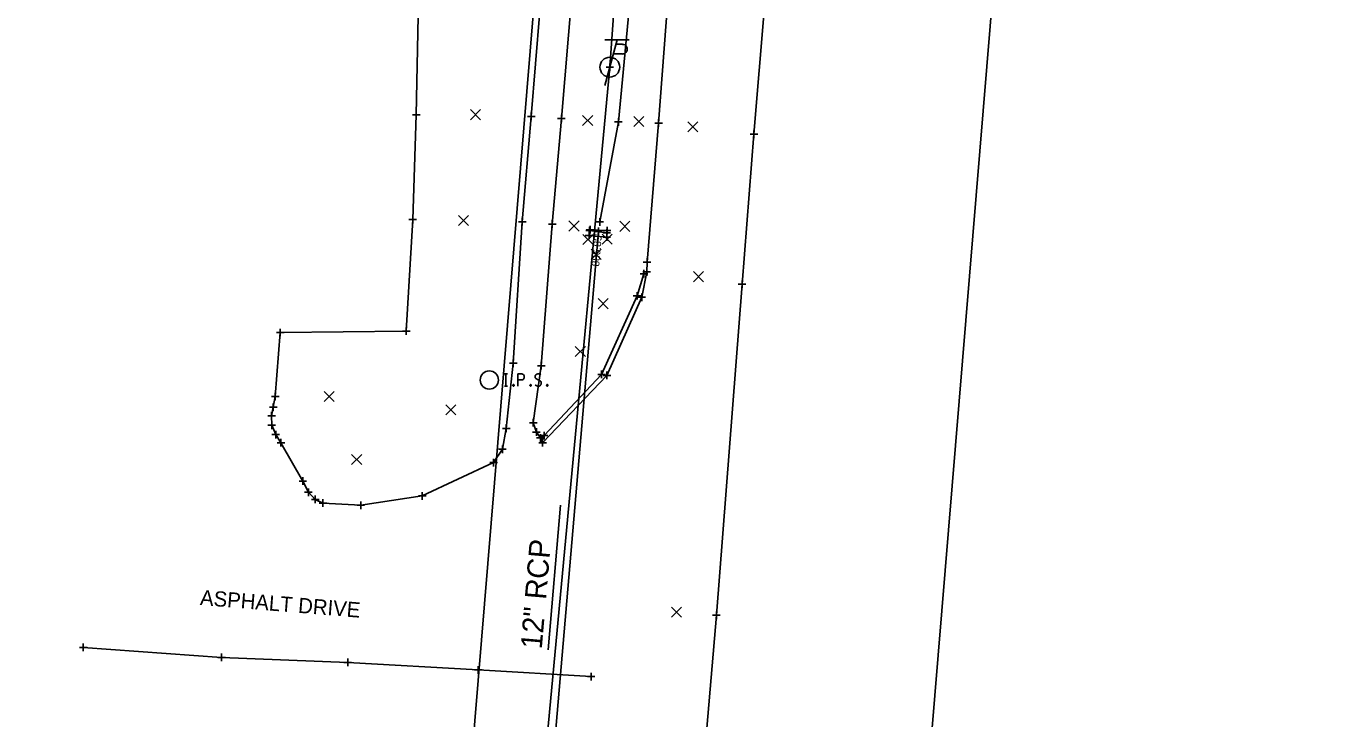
# Model space of a CAD drawing. Extents: x 1380550 to 1381945, y 468927 to 470496.
# Drawn here: x 1381495.3 to 1381668.4, y 469802 to 469893 of the extents above; entities that cross this region are included whole.
import ezdxf

# ---------------------------------------------------------------- set-up
doc = ezdxf.new("R2010")
doc.units = 0
for name, color, linetype in [('DR_X_Ditch', 7, 'Continuous'), ('DR_X_Elev_Flow', 7, 'Continuous'), ('DR_X_Storm_Sewer', 7, 'Continuous'), ('DR_X_Text', 7, 'Continuous'), ('PV_X_COP', 7, 'Continuous'), ('PV_X_Curb', 7, 'Continuous'), ('PV_X_EOP', 7, 'Continuous'), ('PV_X_Walk', 7, 'Continuous'), ('RD_X_Text', 7, 'Continuous'), ('RD_X_Wall', 7, 'Continuous'), ('RW_X_Esmt_General', 7, 'Continuous'), ('SC_Scratch1', 7, 'Continuous'), ('SV_P_Mon_Cells_Set', 7, 'Continuous'), ('SV_X_Break_Lines', 7, 'Continuous'), ('SV_X_Random_Point', 7, 'Continuous'), ('SV_X_Shot_Marker', 7, 'Continuous'), ('UT_X_Electric', 7, 'Continuous'), ('UT_X_Misc_Cells', 7, 'Continuous'), ('UT_X_Telecom', 7, 'Continuous')]:
    doc.layers.add(name, color=color, linetype=linetype)

msp = doc.modelspace()

# ---------------------------------------------------------------- linework, layer by layer
at = {"layer": 'DR_X_Ditch'}
msp.add_lwpolyline([(1381599.49, 470202.78), (1381597.12, 470179.51), (1381597.25, 470175.53), (1381597.2, 470175.03), (1381592.57, 470125.52), (1381589.1, 470072.43), (1381585.65, 470022.01), (1381581.71, 469971.4), (1381577.66, 469928.75), (1381573.1, 469880.44), (1381570.64, 469867.29)], dxfattribs=at)
at = {"layer": 'DR_X_Elev_Flow'}
for p, q in [((1381569.97, 469866.05), (1381570.97, 469866.05)), ((1381570.47, 469866.55), (1381570.47, 469865.55)), ((1381570.47, 469866.05), (1381570.47, 469866.05))]:
    msp.add_line(p, q, dxfattribs=at)
at = {"layer": 'DR_X_Storm_Sewer'}
msp.add_line((1381562.3, 469770.76), (1381570.47, 469866.05), dxfattribs=at)
at = {"layer": 'DR_X_Text'}
msp.add_line((1381565.48, 469830.07), (1381563.85, 469811.05), dxfattribs=at)
at = {"layer": 'PV_X_COP'}
for points in [[(1381627.41, 470324.23), (1381625.02, 470294.42), (1381622.34, 470259.95), (1381618.76, 470220.14), (1381616.92, 470200.19), (1381615.1, 470178.83), (1381610.95, 470124.78), (1381606.49, 470071.23), (1381602.26, 470019.36), (1381598.18, 469969.8), (1381595.01, 469928.06), (1381590.91, 469878.81), (1381589.36, 469859.11), (1381585.99, 469815.58), (1381581.29, 469760.78)], [(1381502.74, 469811.35), (1381520.93, 469810.03), (1381537.52, 469809.37), (1381554.67, 469808.38), (1381569.52, 469807.51)]]:
    msp.add_lwpolyline(points, dxfattribs=at)
at = {"layer": 'PV_X_Curb'}
msp.add_lwpolyline([(1381576.45, 469860.47), (1381575.55, 469857.57), (1381570.89, 469847.25), (1381563.33, 469839.19), (1381562.85, 469838.89)], dxfattribs=at)
at = {"layer": 'PV_X_EOP'}
for points in [[(1381575.39, 470244.04), (1381576.99, 470244.17), (1381579.54, 470245.54), (1381580.63, 470247.96), (1381580.96, 470249.54), (1381591.47, 470243.59), (1381595.25, 470241), (1381599.72, 470235.67), (1381603.29, 470229.19), (1381604.88, 470222.31), (1381604.1, 470201.73), (1381602.36, 470179.43), (1381598.63, 470125.51), (1381593.59, 470071.89), (1381589.53, 470020.65), (1381585.49, 469971.09), (1381582.04, 469928.84), (1381578.38, 469880.28), (1381576.86, 469862.02), (1381576.83, 469860.71), (1381576.16, 469857.38), (1381571.59, 469847.12), (1381563.14, 469838.25)], [(1381550.16, 469977.26), (1381547.52, 469931.2), (1381546.52, 469881.36), (1381546.07, 469867.59), (1381545.21, 469852.93)], [(1381558.35, 469840.14), (1381557.85, 469837.4), (1381556.7, 469835.65), (1381547.32, 469831.26), (1381539.24, 469830.04), (1381534.26, 469830.33), (1381533.24, 469830.81), (1381532.35, 469831.75), (1381531.61, 469833.22), (1381528.74, 469838.25), (1381528.06, 469839.33), (1381527.53, 469840.55), (1381527.51, 469841.81), (1381527.73, 469842.93), (1381527.99, 469844.34), (1381528.64, 469852.75), (1381545.21, 469852.93)], [(1381561.9, 469840.88), (1381562.32, 469839.66), (1381562.85, 469838.89), (1381563.14, 469838.25)]]:
    msp.add_lwpolyline(points, dxfattribs=at)
at = {"layer": 'PV_X_Walk'}
for points in [[(1381595.25, 470241), (1381595.01, 470239.38), (1381594.79, 470235.56), (1381591.94, 470203.13), (1381590.15, 470180.15), (1381585.84, 470126.11), (1381581.45, 470072.84), (1381577.22, 470021.47), (1381573.16, 469971.68), (1381569.7, 469929.43), (1381565.6, 469880.89), (1381564.41, 469867), (1381562.95, 469848.39), (1381561.9, 469840.88)], [(1381542.56, 470237.64), (1381568.34, 470236.69), (1381578.51, 470236.26), (1381584.49, 470236.02), (1381590.64, 470235.62), (1381587.95, 470203.42), (1381586.62, 470180.46), (1381581.93, 470126.46), (1381577.65, 470073.24), (1381573.2, 470021.54), (1381569.15, 469971.74), (1381565.64, 469929.65), (1381561.64, 469881.16), (1381560.46, 469867.32), (1381559.27, 469848.71), (1381558.35, 469840.14)]]:
    msp.add_lwpolyline(points, dxfattribs=at)
at = {"layer": 'RD_X_Wall'}
msp.add_lwpolyline([(1381569.24, 469865.52), (1381569.32, 469866.15), (1381571.58, 469865.85), (1381571.58, 469865.29)], close=True, dxfattribs=at)
at = {"layer": 'RW_X_Esmt_General'}
for points in [[(1381490.4, 469029.46), (1381590.2, 470237.18), (1380558.69, 470277.03)], [(1381783.19, 470213.89), (1381648.78, 470217.49), (1381563.79, 469189.03)]]:
    msp.add_lwpolyline(points, dxfattribs=at)
at = {"layer": 'SV_P_Mon_Cells_Set'}
for points in [[(1381558.14, 469847.3), (1381558.5, 469847.3)], [(1381558.32, 469845.7), (1381558.32, 469847.3)], [(1381559.89, 469845.7), (1381559.89, 469847.3), (1381560.42, 469847.3), (1381560.47, 469847.29), (1381560.55, 469847.26), (1381560.58, 469847.24), (1381560.61, 469847.21), (1381560.66, 469847.15), (1381560.69, 469847.08), (1381560.71, 469846.98), (1381560.71, 469846.83), (1381560.7, 469846.78), (1381560.68, 469846.71), (1381560.64, 469846.62), (1381560.59, 469846.58), (1381560.56, 469846.56), (1381560.5, 469846.53), (1381560.42, 469846.52), (1381559.89, 469846.52)], [(1381562.9, 469847.18), (1381562.87, 469847.21), (1381562.84, 469847.24), (1381562.74, 469847.27), (1381562.62, 469847.3), (1381562.53, 469847.3), (1381562.5, 469847.3), (1381562.36, 469847.26), (1381562.23, 469847.18), (1381562.16, 469847.08), (1381562.14, 469846.98), (1381562.14, 469846.91), (1381562.16, 469846.81), (1381562.25, 469846.72), (1381562.85, 469846.34), (1381562.91, 469846.29), (1381562.93, 469846.24), (1381562.95, 469846.16), (1381562.95, 469846.09), (1381562.94, 469846.01), (1381562.93, 469845.96), (1381562.91, 469845.9), (1381562.88, 469845.85), (1381562.86, 469845.81), (1381562.83, 469845.77), (1381562.8, 469845.75), (1381562.75, 469845.72), (1381562.72, 469845.71), (1381562.62, 469845.7), (1381562.47, 469845.7), (1381562.37, 469845.72), (1381562.22, 469845.81), (1381562.14, 469845.89)], [(1381558.14, 469845.7), (1381558.5, 469845.7)], [(1381559.28, 469845.91), (1381559.34, 469845.91), (1381559.37, 469845.89), (1381559.4, 469845.84), (1381559.4, 469845.77), (1381559.37, 469845.72), (1381559.34, 469845.7), (1381559.28, 469845.7), (1381559.25, 469845.72), (1381559.21, 469845.77), (1381559.21, 469845.84), (1381559.25, 469845.89), (1381559.28, 469845.91)], [(1381561.53, 469845.91), (1381561.58, 469845.91), (1381561.62, 469845.89), (1381561.65, 469845.84), (1381561.65, 469845.77), (1381561.62, 469845.72), (1381561.58, 469845.7), (1381561.53, 469845.7), (1381561.5, 469845.72), (1381561.46, 469845.77), (1381561.46, 469845.84), (1381561.5, 469845.89), (1381561.53, 469845.91)], [(1381563.71, 469845.91), (1381563.77, 469845.91), (1381563.8, 469845.89), (1381563.83, 469845.84), (1381563.83, 469845.77), (1381563.8, 469845.72), (1381563.77, 469845.7), (1381563.71, 469845.7), (1381563.68, 469845.72), (1381563.65, 469845.77), (1381563.65, 469845.84), (1381563.68, 469845.89), (1381563.71, 469845.91)]]:
    msp.add_lwpolyline(points, dxfattribs=at)
msp.add_circle((1381556.13, 469846.5), 1.2, dxfattribs=at)
at = {"layer": 'SV_X_Break_Lines'}
msp.add_lwpolyline([(1381569.38, 469866.27), (1381571.6, 469866.16)], dxfattribs=at)
at = {"layer": 'SV_X_Random_Point'}
for p, q in [((1381553.66, 469880.73), (1381554.99, 469882.07)), ((1381553.66, 469882.07), (1381554.99, 469880.73)), ((1381568.38, 469879.95), (1381569.72, 469881.29)), ((1381568.38, 469881.29), (1381569.72, 469879.95)), ((1381575.11, 469879.83), (1381576.44, 469881.16)), ((1381575.11, 469881.16), (1381576.44, 469879.83)), ((1381582.21, 469879.12), (1381583.54, 469880.46)), ((1381582.21, 469880.46), (1381583.54, 469879.12)), ((1381552.08, 469866.8), (1381553.41, 469868.13)), ((1381552.08, 469868.13), (1381553.41, 469866.8)), ((1381566.59, 469866.09), (1381567.92, 469867.43)), ((1381566.59, 469867.43), (1381567.92, 469866.09)), ((1381573.28, 469866.03), (1381574.61, 469867.37)), ((1381573.28, 469867.37), (1381574.61, 469866.03)), ((1381568.43, 469864.32), (1381569.76, 469865.65)), ((1381568.43, 469865.65), (1381569.76, 469864.32)), ((1381570.96, 469864.35), (1381572.29, 469865.68)), ((1381570.96, 469865.68), (1381572.29, 469864.35)), ((1381569.51, 469862.37), (1381570.84, 469863.7)), ((1381569.51, 469863.7), (1381570.84, 469862.37)), ((1381582.96, 469859.41), (1381584.29, 469860.75)), ((1381582.96, 469860.75), (1381584.29, 469859.41)), ((1381570.42, 469855.88), (1381571.76, 469857.21)), ((1381570.42, 469857.21), (1381571.76, 469855.88)), ((1381567.42, 469849.58), (1381568.76, 469850.92)), ((1381567.42, 469850.92), (1381568.76, 469849.58)), ((1381534.4, 469843.66), (1381535.73, 469845)), ((1381534.4, 469845), (1381535.73, 469843.66)), ((1381550.4, 469841.93), (1381551.73, 469843.26)), ((1381550.4, 469843.26), (1381551.73, 469841.93)), ((1381538.02, 469835.38), (1381539.35, 469836.71)), ((1381538.02, 469836.71), (1381539.35, 469835.38)), ((1381580.06, 469815.31), (1381581.4, 469816.64)), ((1381580.06, 469816.64), (1381581.4, 469815.31))]:
    msp.add_line(p, q, dxfattribs=at)
at = {"layer": 'SV_X_Shot_Marker'}
for p, q in [((1381571.97, 469888.14), (1381571.97, 469887.14)), ((1381571.97, 469888.14), (1381571.97, 469887.14)), ((1381571.47, 469887.64), (1381572.47, 469887.64)), ((1381571.47, 469887.64), (1381572.47, 469887.64)), ((1381571.97, 469887.64), (1381571.97, 469887.64)), ((1381571.97, 469887.64), (1381571.97, 469887.64)), ((1381546.02, 469881.36), (1381547.02, 469881.36)), ((1381546.52, 469881.86), (1381546.52, 469880.86)), ((1381546.52, 469881.36), (1381546.52, 469881.36)), ((1381561.14, 469881.16), (1381562.14, 469881.16)), ((1381561.64, 469881.66), (1381561.64, 469880.66)), ((1381561.64, 469881.16), (1381561.64, 469881.16)), ((1381565.1, 469880.89), (1381566.1, 469880.89)), ((1381565.6, 469881.39), (1381565.6, 469880.39)), ((1381565.6, 469880.89), (1381565.6, 469880.89)), ((1381573.1, 469880.94), (1381573.1, 469879.94)), ((1381578.38, 469880.78), (1381578.38, 469879.78)), ((1381572.6, 469880.44), (1381573.6, 469880.44)), ((1381573.1, 469880.44), (1381573.1, 469880.44)), ((1381577.88, 469880.28), (1381578.88, 469880.28)), ((1381578.38, 469880.28), (1381578.38, 469880.28)), ((1381590.91, 469879.31), (1381590.91, 469878.31)), ((1381590.41, 469878.81), (1381591.41, 469878.81)), ((1381590.91, 469878.81), (1381590.91, 469878.81)), ((1381545.57, 469867.59), (1381546.57, 469867.59)), ((1381546.07, 469868.09), (1381546.07, 469867.09)), ((1381546.07, 469867.59), (1381546.07, 469867.59)), ((1381559.96, 469867.32), (1381560.96, 469867.32)), ((1381560.46, 469867.82), (1381560.46, 469866.82)), ((1381560.46, 469867.32), (1381560.46, 469867.32)), ((1381563.91, 469867), (1381564.91, 469867)), ((1381564.41, 469867.5), (1381564.41, 469866.5)), ((1381564.41, 469867), (1381564.41, 469867)), ((1381570.14, 469867.29), (1381571.14, 469867.29)), ((1381570.64, 469867.79), (1381570.64, 469866.79)), ((1381570.64, 469867.29), (1381570.64, 469867.29)), ((1381568.74, 469865.52), (1381569.74, 469865.52)), ((1381568.82, 469866.15), (1381569.82, 469866.15)), ((1381568.88, 469866.27), (1381569.88, 469866.27)), ((1381569.24, 469866.02), (1381569.24, 469865.02)), ((1381569.24, 469865.52), (1381569.24, 469865.52)), ((1381569.32, 469866.65), (1381569.32, 469865.65)), ((1381569.32, 469866.15), (1381569.32, 469866.15)), ((1381569.38, 469866.77), (1381569.38, 469865.77)), ((1381569.38, 469866.27), (1381569.38, 469866.27)), ((1381571.08, 469865.85), (1381572.08, 469865.85)), ((1381571.08, 469865.29), (1381572.08, 469865.29)), ((1381571.1, 469866.16), (1381572.1, 469866.16)), ((1381571.58, 469866.35), (1381571.58, 469865.35)), ((1381571.58, 469865.85), (1381571.58, 469865.85)), ((1381571.58, 469865.79), (1381571.58, 469864.79)), ((1381571.58, 469865.29), (1381571.58, 469865.29)), ((1381571.6, 469866.66), (1381571.6, 469865.66)), ((1381571.6, 469866.16), (1381571.6, 469866.16)), ((1381576.36, 469862.02), (1381577.36, 469862.02)), ((1381576.86, 469862.52), (1381576.86, 469861.52)), ((1381576.86, 469862.02), (1381576.86, 469862.02)), ((1381575.95, 469860.47), (1381576.95, 469860.47)), ((1381576.33, 469860.71), (1381577.33, 469860.71)), ((1381576.45, 469860.97), (1381576.45, 469859.97)), ((1381576.45, 469860.47), (1381576.45, 469860.47)), ((1381576.83, 469861.21), (1381576.83, 469860.21)), ((1381576.83, 469860.71), (1381576.83, 469860.71)), ((1381588.86, 469859.11), (1381589.86, 469859.11)), ((1381589.36, 469859.61), (1381589.36, 469858.61)), ((1381589.36, 469859.11), (1381589.36, 469859.11)), ((1381575.05, 469857.57), (1381576.05, 469857.57)), ((1381575.05, 469857.57), (1381576.05, 469857.57)), ((1381575.55, 469858.07), (1381575.55, 469857.07)), ((1381575.55, 469858.07), (1381575.55, 469857.07)), ((1381575.55, 469857.57), (1381575.55, 469857.57)), ((1381575.55, 469857.57), (1381575.55, 469857.57)), ((1381575.66, 469857.38), (1381576.66, 469857.38)), ((1381575.66, 469857.38), (1381576.66, 469857.38)), ((1381576.16, 469857.88), (1381576.16, 469856.88)), ((1381576.16, 469857.88), (1381576.16, 469856.88)), ((1381576.16, 469857.38), (1381576.16, 469857.38)), ((1381576.16, 469857.38), (1381576.16, 469857.38)), ((1381528.64, 469853.25), (1381528.64, 469852.25)), ((1381545.21, 469853.43), (1381545.21, 469852.43)), ((1381545.21, 469853.43), (1381545.21, 469852.43)), ((1381528.14, 469852.75), (1381529.14, 469852.75)), ((1381528.64, 469852.75), (1381528.64, 469852.75)), ((1381544.71, 469852.93), (1381545.71, 469852.93)), ((1381544.71, 469852.93), (1381545.71, 469852.93)), ((1381545.21, 469852.93), (1381545.21, 469852.93)), ((1381545.21, 469852.93), (1381545.21, 469852.93)), ((1381558.77, 469848.71), (1381559.77, 469848.71)), ((1381559.27, 469849.21), (1381559.27, 469848.21)), ((1381559.27, 469848.71), (1381559.27, 469848.71)), ((1381562.45, 469848.39), (1381563.45, 469848.39)), ((1381562.95, 469848.89), (1381562.95, 469847.89)), ((1381562.95, 469848.39), (1381562.95, 469848.39)), ((1381570.39, 469847.25), (1381571.39, 469847.25)), ((1381570.89, 469847.75), (1381570.89, 469846.75)), ((1381570.89, 469847.25), (1381570.89, 469847.25)), ((1381571.09, 469847.12), (1381572.09, 469847.12)), ((1381571.59, 469847.62), (1381571.59, 469846.62)), ((1381571.59, 469847.12), (1381571.59, 469847.12)), ((1381527.99, 469844.84), (1381527.99, 469843.84)), ((1381527.23, 469842.93), (1381528.23, 469842.93)), ((1381527.49, 469844.34), (1381528.49, 469844.34)), ((1381527.73, 469843.43), (1381527.73, 469842.43)), ((1381527.73, 469842.93), (1381527.73, 469842.93)), ((1381527.99, 469844.34), (1381527.99, 469844.34)), ((1381527.01, 469841.81), (1381528.01, 469841.81)), ((1381527.51, 469842.31), (1381527.51, 469841.31)), ((1381527.51, 469841.81), (1381527.51, 469841.81)), ((1381527.53, 469841.05), (1381527.53, 469840.05)), ((1381561.9, 469841.38), (1381561.9, 469840.38)), ((1381561.9, 469841.38), (1381561.9, 469840.38)), ((1381527.03, 469840.55), (1381528.03, 469840.55)), ((1381527.53, 469840.55), (1381527.53, 469840.55)), ((1381527.56, 469839.33), (1381528.56, 469839.33)), ((1381528.06, 469839.83), (1381528.06, 469838.83)), ((1381528.06, 469839.33), (1381528.06, 469839.33)), ((1381557.85, 469840.14), (1381558.85, 469840.14)), ((1381557.85, 469840.14), (1381558.85, 469840.14)), ((1381558.35, 469840.64), (1381558.35, 469839.64)), ((1381558.35, 469840.64), (1381558.35, 469839.64)), ((1381558.35, 469840.14), (1381558.35, 469840.14)), ((1381558.35, 469840.14), (1381558.35, 469840.14)), ((1381561.4, 469840.88), (1381562.4, 469840.88)), ((1381561.4, 469840.88), (1381562.4, 469840.88)), ((1381561.82, 469839.66), (1381562.82, 469839.66)), ((1381561.9, 469840.88), (1381561.9, 469840.88)), ((1381561.9, 469840.88), (1381561.9, 469840.88)), ((1381562.32, 469840.16), (1381562.32, 469839.16)), ((1381562.32, 469839.66), (1381562.32, 469839.66)), ((1381562.85, 469839.39), (1381562.85, 469838.39)), ((1381562.85, 469839.39), (1381562.85, 469838.39)), ((1381563.33, 469839.69), (1381563.33, 469838.69)), ((1381563.33, 469839.69), (1381563.33, 469838.69)), ((1381528.24, 469838.25), (1381529.24, 469838.25)), ((1381528.74, 469838.75), (1381528.74, 469837.75)), ((1381528.74, 469838.25), (1381528.74, 469838.25)), ((1381557.85, 469837.9), (1381557.85, 469836.9)), ((1381562.35, 469838.89), (1381563.35, 469838.89)), ((1381562.35, 469838.89), (1381563.35, 469838.89)), ((1381562.64, 469838.25), (1381563.64, 469838.25)), ((1381562.64, 469838.25), (1381563.64, 469838.25)), ((1381562.83, 469839.19), (1381563.83, 469839.19)), ((1381562.83, 469839.19), (1381563.83, 469839.19)), ((1381562.85, 469838.89), (1381562.85, 469838.89)), ((1381562.85, 469838.89), (1381562.85, 469838.89)), ((1381563.14, 469838.75), (1381563.14, 469837.75)), ((1381563.14, 469838.75), (1381563.14, 469837.75)), ((1381563.14, 469838.25), (1381563.14, 469838.25)), ((1381563.14, 469838.25), (1381563.14, 469838.25)), ((1381563.33, 469839.19), (1381563.33, 469839.19)), ((1381563.33, 469839.19), (1381563.33, 469839.19)), ((1381556.7, 469836.15), (1381556.7, 469835.15)), ((1381557.35, 469837.4), (1381558.35, 469837.4)), ((1381557.85, 469837.4), (1381557.85, 469837.4)), ((1381556.2, 469835.65), (1381557.2, 469835.65)), ((1381556.7, 469835.65), (1381556.7, 469835.65)), ((1381531.11, 469833.22), (1381532.11, 469833.22)), ((1381531.61, 469833.72), (1381531.61, 469832.72)), ((1381531.61, 469833.22), (1381531.61, 469833.22)), ((1381531.85, 469831.75), (1381532.85, 469831.75)), ((1381532.35, 469832.25), (1381532.35, 469831.25)), ((1381532.35, 469831.75), (1381532.35, 469831.75)), ((1381532.74, 469830.81), (1381533.74, 469830.81)), ((1381533.24, 469831.31), (1381533.24, 469830.31)), ((1381533.24, 469830.81), (1381533.24, 469830.81)), ((1381534.26, 469830.83), (1381534.26, 469829.83)), ((1381534.26, 469830.83), (1381534.26, 469829.83)), ((1381539.24, 469830.54), (1381539.24, 469829.54)), ((1381546.82, 469831.26), (1381547.82, 469831.26)), ((1381546.82, 469831.26), (1381547.82, 469831.26)), ((1381547.32, 469831.76), (1381547.32, 469830.76)), ((1381547.32, 469831.76), (1381547.32, 469830.76)), ((1381547.32, 469831.26), (1381547.32, 469831.26)), ((1381547.32, 469831.26), (1381547.32, 469831.26)), ((1381533.76, 469830.33), (1381534.76, 469830.33)), ((1381533.76, 469830.33), (1381534.76, 469830.33)), ((1381534.26, 469830.33), (1381534.26, 469830.33)), ((1381534.26, 469830.33), (1381534.26, 469830.33)), ((1381538.74, 469830.04), (1381539.74, 469830.04)), ((1381539.24, 469830.04), (1381539.24, 469830.04)), ((1381585.49, 469815.58), (1381586.49, 469815.58)), ((1381585.99, 469816.08), (1381585.99, 469815.08)), ((1381585.99, 469815.58), (1381585.99, 469815.58)), ((1381502.74, 469811.85), (1381502.74, 469810.85)), ((1381502.24, 469811.35), (1381503.24, 469811.35)), ((1381502.74, 469811.35), (1381502.74, 469811.35)), ((1381520.43, 469810.03), (1381521.43, 469810.03)), ((1381520.93, 469810.53), (1381520.93, 469809.53)), ((1381520.93, 469810.03), (1381520.93, 469810.03)), ((1381537.52, 469809.87), (1381537.52, 469808.87)), ((1381537.02, 469809.37), (1381538.02, 469809.37)), ((1381537.52, 469809.37), (1381537.52, 469809.37)), ((1381554.17, 469808.38), (1381555.17, 469808.38)), ((1381554.67, 469808.88), (1381554.67, 469807.88)), ((1381554.67, 469808.38), (1381554.67, 469808.38)), ((1381569.02, 469807.51), (1381570.02, 469807.51)), ((1381569.52, 469808.01), (1381569.52, 469807.01)), ((1381569.52, 469807.51), (1381569.52, 469807.51))]:
    msp.add_line(p, q, dxfattribs=at)
at = {"layer": 'UT_X_Electric'}
msp.add_lwpolyline([(1381665.56, 470247.4), (1381595.79, 470220.83), (1381581.26, 470018.2), (1381571.97, 469887.64), (1381559.77, 469757.41), (1381543.86, 469565.78), (1381529.17, 469390.12), (1381515.28, 469203.1), (1381540.8, 469054.26)], dxfattribs=at)
at = {"layer": 'UT_X_Misc_Cells'}
for p, q in [((1381572.93, 469891.24), (1381571.32, 469885.24)), ((1381574.53, 469891.24), (1381571.33, 469891.24)), ((1381572.77, 469890.64), (1381573.62, 469890.64)), ((1381572.43, 469889.37), (1381573.62, 469889.37))]:
    msp.add_line(p, q, dxfattribs=at)
msp.add_circle((1381571.97, 469887.64), 1.3, dxfattribs=at)
msp.add_arc((1381573.63, 469890), 0.638, 268.8767, 91.1233, dxfattribs=at)
at = {"layer": 'UT_X_Telecom'}
msp.add_lwpolyline([(1381665.56, 470247.4), (1381595.35, 470217.51), (1381581.26, 470018.2), (1381571.97, 469887.64), (1381559.77, 469757.41), (1381543.86, 469565.78), (1381529.17, 469390.12), (1381515.28, 469203.1), (1381540.8, 469054.26)], dxfattribs=at)

# ---------------------------------------------------------------- texts
at = {"layer": 'DR_X_Text'}
msp.add_text('12" RCP', height=2.8, rotation=85.1034, dxfattribs=at).set_placement((1381563.02, 469811.06))
at = {"layer": 'RD_X_Text'}
msp.add_text('ASPHALT DRIVE', height=2, rotation=355.4428, dxfattribs=at).set_placement((1381518.05, 469816.93))
at = {"layer": 'SC_Scratch1'}
msp.add_text("886.89'", height=1, rotation=85.1034, dxfattribs=at).set_placement((1381570.57, 469861.4))

doc.saveas('drawing.dxf')
